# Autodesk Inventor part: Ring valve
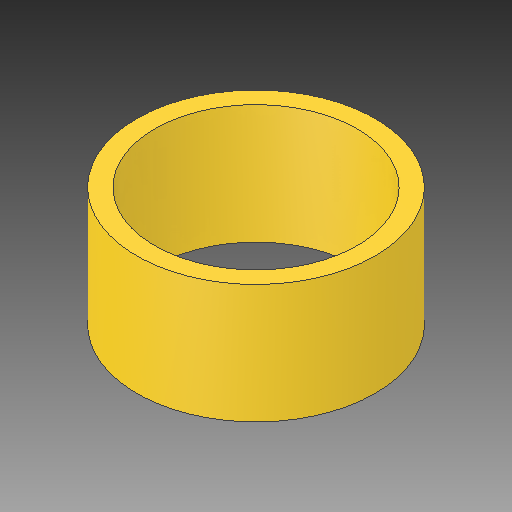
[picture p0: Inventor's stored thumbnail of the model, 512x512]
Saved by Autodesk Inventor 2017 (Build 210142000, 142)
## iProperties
Created: 2020-04
Part Number: Ring valve
Material: Generic
Document SubType Name: Modeling
Designer: user
Density: 1 g/cm^3
Appearance: Default
Mass: 0.871792 g
Surface Area: 13.3675 cm^2
Volume: 0.871792 cm^3
Author: user
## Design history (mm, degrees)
sketch "Sketch1"
  geometry: C1 r 10 at (0, 0); C2 r 8.5 at (0, 0); 1 further point
  constraints: 2 centre point, 1 coincident
  dimensions: "d0" = 20 diameter of C1; "d1" = 1.5 radial gap between concentric circles of C1 C2
extrude "Extrusion1" new body sketch "Sketch1" distance "d2" = 10; taper "d3" = 0 deg
body "Solid1"
